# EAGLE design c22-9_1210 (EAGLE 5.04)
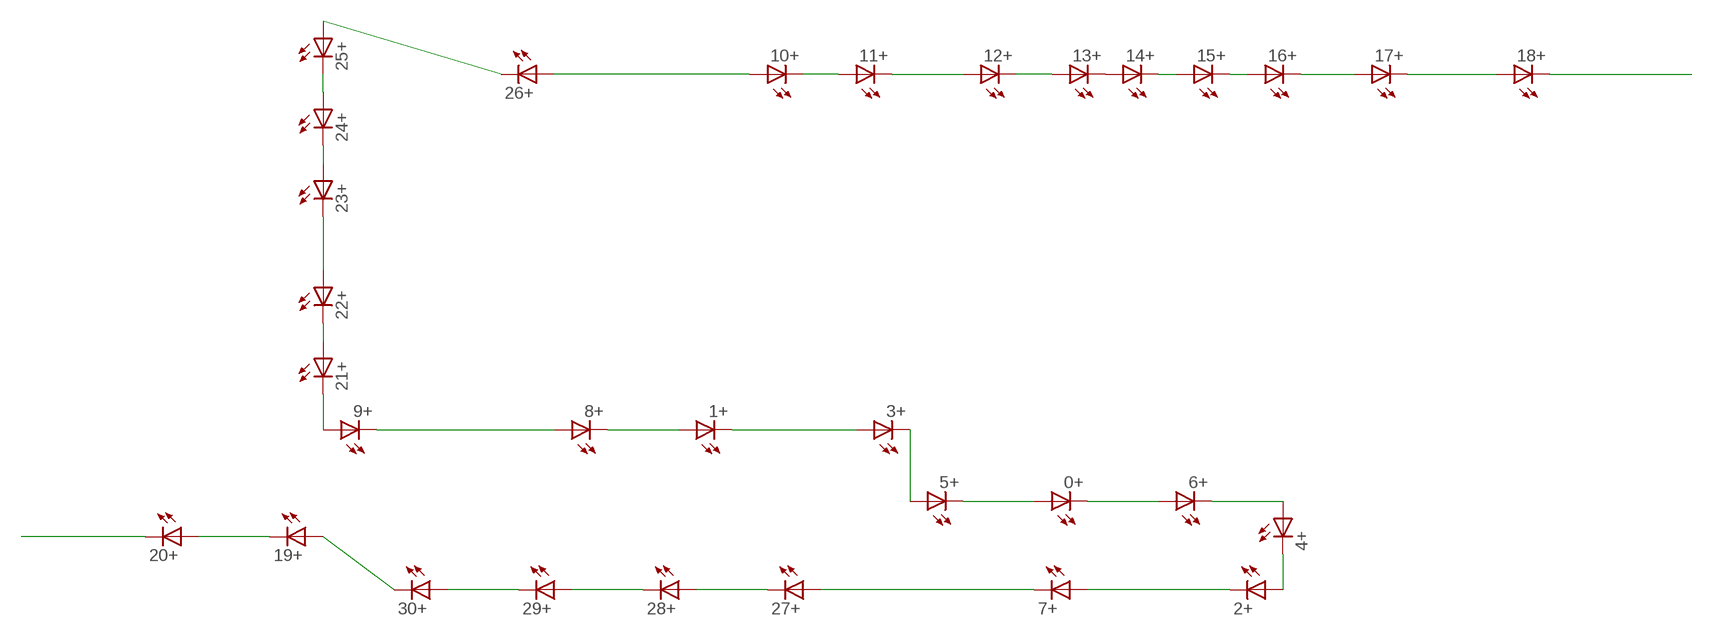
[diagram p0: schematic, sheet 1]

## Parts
0+  LED1210  [1210]
1+  LED1210  [1210]
2+  LED1210  [1210]
3+  LED1210  [1210]
4+  LED1210  [1210]
5+  LED1210  [1210]
6+  LED1210  [1210]
7+  LED1210  [1210]
8+  LED1210  [1210]
9+  LED1210  [1210]
10+  LED1210  [1210]
11+  LED1210  [1210]
12+  LED1210  [1210]
13+  LED1210  [1210]
14+  LED1210  [1210]
15+  LED1210  [1210]
16+  LED1210  [1210]
17+  LED1210  [1210]
18+  LED1210  [1210]
19+  LED1210  [1210]
20+  LED1210  [1210]
21+  LED1210  [1210]
22+  LED1210  [1210]
23+  LED1210  [1210]
24+  LED1210  [1210]
25+  LED1210  [1210]
26+  LED1210  [1210]
27+  LED1210  [1210]
28+  LED1210  [1210]
29+  LED1210  [1210]
30+  LED1210  [1210]

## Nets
MINUS: 20+.P$2(C)
MINUS9: 18+.P$2(C)
N$1: 16+.P$2(C) 17+.P$1(A)
N$2: 19+.P$2(C) 20+.P$1(A)
N$3: 11+.P$2(C) 12+.P$1(A)
N$4: 19+.P$1(A) 30+.P$2(C)
N$5: 10+.P$2(C) 11+.P$1(A)
N$6: 8+.P$1(A) 9+.P$2(C)
N$7: 29+.P$2(C) 30+.P$1(A)
N$8: 28+.P$2(C) 29+.P$1(A)
N$9: 27+.P$2(C) 28+.P$1(A)
N$10: 14+.P$2(C) 15+.P$1(A)
N$11: 13+.P$2(C) 14+.P$1(A)
N$12: 2+.P$2(C) 7+.P$1(A)
N$13: 7+.P$2(C) 27+.P$1(A)
N$14: 2+.P$1(A) 4+.P$2(C)
N$15: 4+.P$1(A) 6+.P$2(C)
N$16: 0+.P$2(C) 6+.P$1(A)
N$17: 0+.P$1(A) 5+.P$2(C)
N$18: 3+.P$2(C) 5+.P$1(A)
N$19: 1+.P$2(C) 3+.P$1(A)
N$20: 1+.P$1(A) 8+.P$2(C)
N$21: 17+.P$2(C) 18+.P$1(A)
N$23: 9+.P$1(A) 21+.P$2(C)
N$24: 21+.P$1(A) 22+.P$2(C)
N$25: 22+.P$1(A) 23+.P$2(C)
N$26: 24+.P$1(A) 25+.P$2(C)
N$27: 25+.P$1(A) 26+.P$2(C)
N$28: 23+.P$1(A) 24+.P$2(C)
N$30: 15+.P$2(C) 16+.P$1(A)
N$32: 12+.P$2(C) 13+.P$1(A)
PLUS: 10+.P$1(A) 26+.P$1(A)

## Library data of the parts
0+ 1+ 2+ 3+ 4+ 5+ 6+ 7+ 8+ 9+ 10+ 11+ 12+ 13+ 14+ 15+ 16+ 17+ 18+ 19+ 20+ 21+ 22+ 23+ 24+ 25+ 26+ 27+ 28+ 29+ 30+ = led(2):LED: LED

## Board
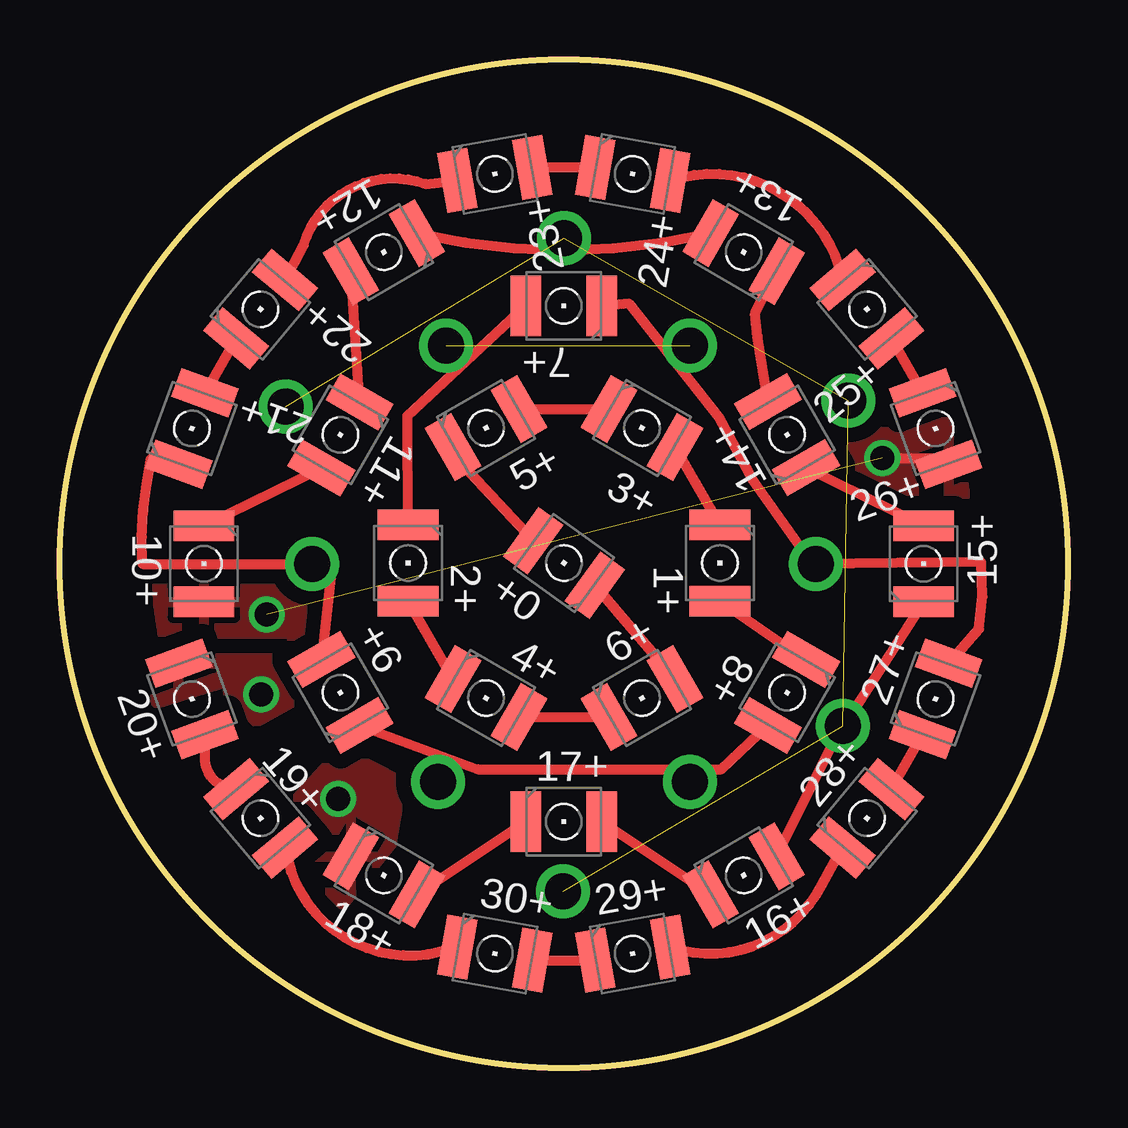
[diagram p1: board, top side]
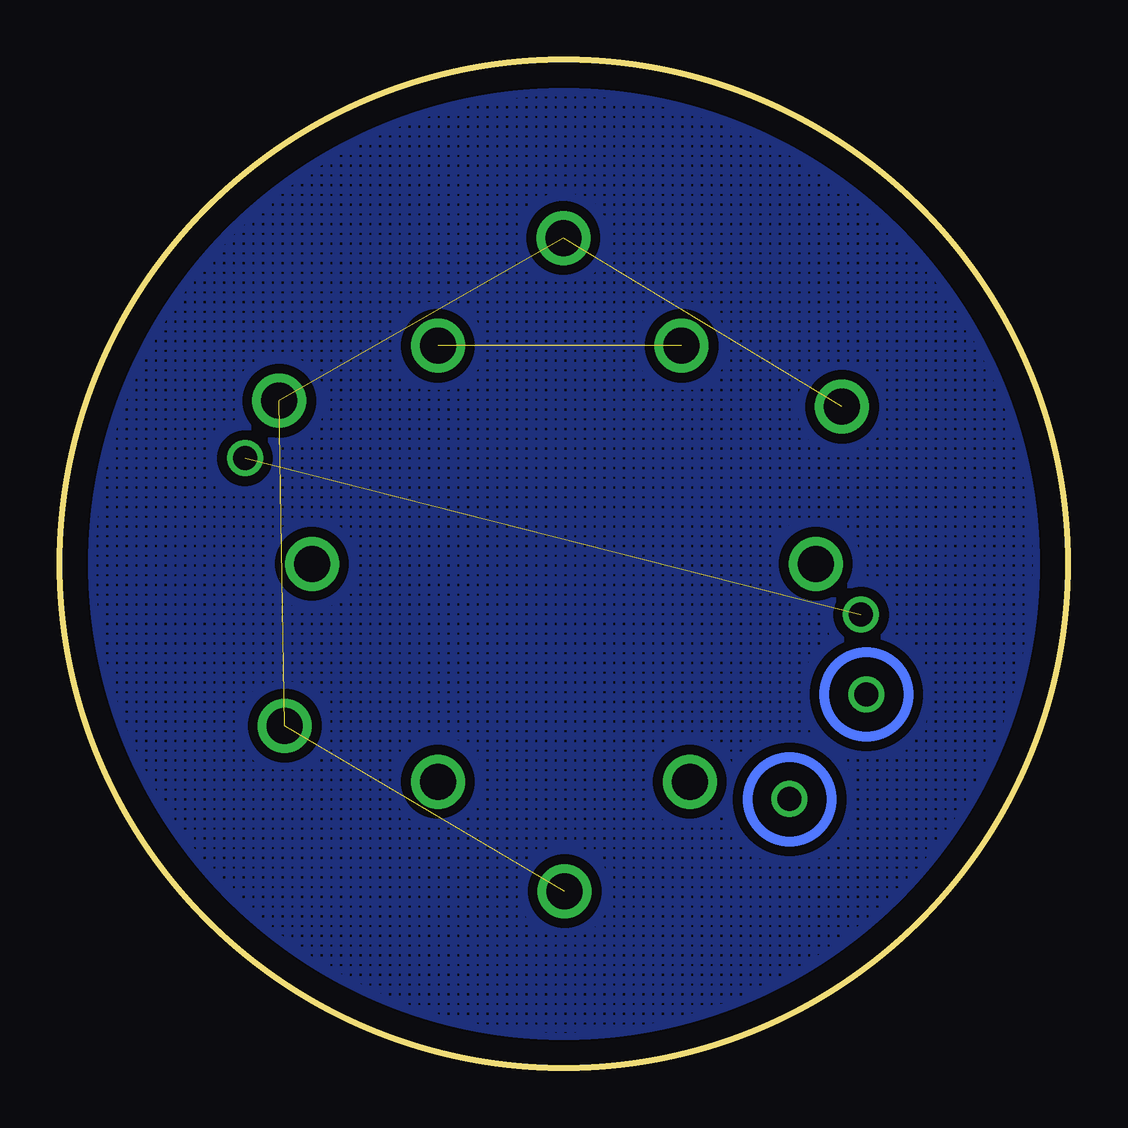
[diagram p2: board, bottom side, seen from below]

Size 42 x 42 mm. Coordinates in mm from the lower left corner, seen from the top.
Outline: circle at 21,21 radius 21
Copper layers (1*16): Top 0.035mm / dielectric 1.5mm / Bottom 0.035mm
Design rules "default": minimum track width 10mil, minimum drill 24mil, track to track 8mil, track to pad 8mil, pad to pad 8mil, via to via 8mil, smd to smd 8mil, copper to edge 40mil, drill to drill 8mil, minimum pad ring 10mil, minimum via ring 8mil, stop-mask expansion 4mil, vias tented up to drill 0mil, thermal gap 10mil

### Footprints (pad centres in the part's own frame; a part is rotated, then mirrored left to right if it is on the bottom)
1210 = smd 1.27 x 2.54: P$1 1.587,0; P$2 -1.587,0

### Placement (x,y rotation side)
0+  21.01,21.03 144.1 top
1+  27.51,21.03 270 top
2+  14.51,21.03 270 top
3+  24.26,26.66 330 top
4+  17.76,15.4 330 top
5+  17.76,26.66 30 top
6+  24.26,15.4 30 top
7+  21,31.75 180 top
8+  30.31,15.63 240 top
9+  11.69,15.63 120 top
10+  6,21 270 top
11+  11.69,26.37 240 top
12+  13.5,33.99 210 top
13+  28.5,33.99 150 top
14+  30.31,26.38 120 top
15+  36,21 90 top
16+  28.5,8.01 30 top
17+  21,10.25 0 top
18+  13.5,8.01 330 top
19+  8.36,10.39 310 top
20+  5.5,15.36 290 top
21+  5.5,26.64 70 top
22+  8.36,31.61 50 top
23+  18.13,37.25 10 top
24+  23.87,37.25 350 top
25+  33.64,31.61 310 top
26+  36.5,26.64 290 top
27+  36.5,15.36 70 top
28+  33.64,10.39 50 top
29+  23.87,4.75 10 top
30+  18.13,4.75 350 top

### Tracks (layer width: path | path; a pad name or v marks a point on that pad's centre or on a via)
H$29  (via drill 1.5)  (4 unrouted)
  other vias: 32.86,27.8 9.4,27.55 21.02,34.58 32.63,14.24 20.96,7.35
MINUS  (via drill 1)
  other vias: 8.38,15.56
  pour Top (isolate 0.61, rank 3): 4.73,17.08 8.82,17.08 9.79,15.26 8.18,14.37 7.01,15.54 7.01,16.07 4.03,15.16 3.62,16.15
MINUS9  (via drill 1)
  other vias: 11.59,11.19
  pour Top (isolate 0.61): 13.81,9.28 11.66,6.59 9.34,10.68 11.71,13.26 14.27,11.93
N$1
  Top 0.406: 17+.P$1 16+.P$2
N$2
  Top 0.406: 19+.P$2 arc-90 6.04,12.9 20+.P$1
N$3
  Top 0.406: 11+.P$2 12+.P$1
N$4
  Top 0.406: 19+.P$1 arc90 15.34,4.73 30+.P$2
N$5
  Top 0.406: 10+.P$2 11+.P$1
N$6
  Top 0.406: 9+.P$2 17.42,12.43 27.58,12.43 8+.P$1
N$7
  Top 0.406: 30+.P$1 29+.P$2
N$8
  Top 0.406: 29+.P$1 arc82 31.75,7.62 28+.P$2
N$9
  Top 0.406: 28+.P$1 27+.P$2
N$10
  Top 0.406: 14+.P$2 15+.P$1
N$11
  Top 0.406: 14+.P$1 29.08,30.48 28.97,31.45 13+.P$2
N$12
  Top 0.406: 7+.P$1 14.48,27.16 2+.P$2
N$13
  Top 0.406: 27+.P$1 38.31,18.27 38.45,19.63 38.4,21.07 31.36,21 28.91,24.44 27.47,27.11 23.73,31.84 7+.P$2
N$14
  Top 0.406: 4+.P$2 2+.P$1
N$15
  Top 0.406: 4+.P$1 6+.P$2
N$16
  Top 0.406: 0+.P$2 6+.P$1
N$17
  Top 0.406: 0+.P$1 16.51,25.4 5+.P$2
N$18
  Top 0.406: 5+.P$1 3+.P$2
N$19
  Top 0.406: 1+.P$2 3+.P$1
N$20
  Top 0.406: 1+.P$1 31.75,16.51 8+.P$2
N$21
  Top 0.406: 18+.P$1 17+.P$2
N$22  (via drill 1.5)  (1 unrouted)
  other vias: 26.25,30.09 16.09,30.09
N$23
  Top 0.406: 9+.P$1 11.34,21 3.43,21 arc-15 3.81,25.4 21+.P$2
N$24
  Top 0.406: 22+.P$2 21+.P$1
N$25
  Top 0.406: 22+.P$1 10.16,34.29 arc-93 15.24,36.83 23+.P$2
N$26
  Top 0.406: 24+.P$1 arc-97 25+.P$2
N$27
  Top 0.406: 25+.P$1 26+.P$2
N$28
  Top 0.406: 23+.P$1 24+.P$2
N$29
  pour Bottom (isolate 0.406, hatched): 20.32,41.91 30.48,40.64 arc-23 41.91,26.67 40.64,12.7 arc-29 30.48,2.54 arc-64 12.7,2.54 7.62,5.08 arc-74 1.27,25.4 arc-95
N$30
  Top 0.406: 16+.P$1 32.31,13.65 15+.P$2
N$31  (via drill 1.5)
  other vias: 10.5,21
N$32
  Top 0.406: 12+.P$2 arc27 13+.P$1
N$33  (via drill 1.5)
  other vias: 15.75,11.91
N$34  (via drill 1.5)
  other vias: 26.25,11.91
N$35  (via drill 1.5)
  other vias: 31.5,21
PLUS  (via drill 1)  (1 unrouted)
  Top 0.406: v34.29,25.4 36.83,25.4
  other vias: 8.61,18.88
  pour Top (isolate 0.61, rank 4): 21,38 arc180 21,4 arc180
(copper drawn outside any net)
  shapes: Bottom circle x2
